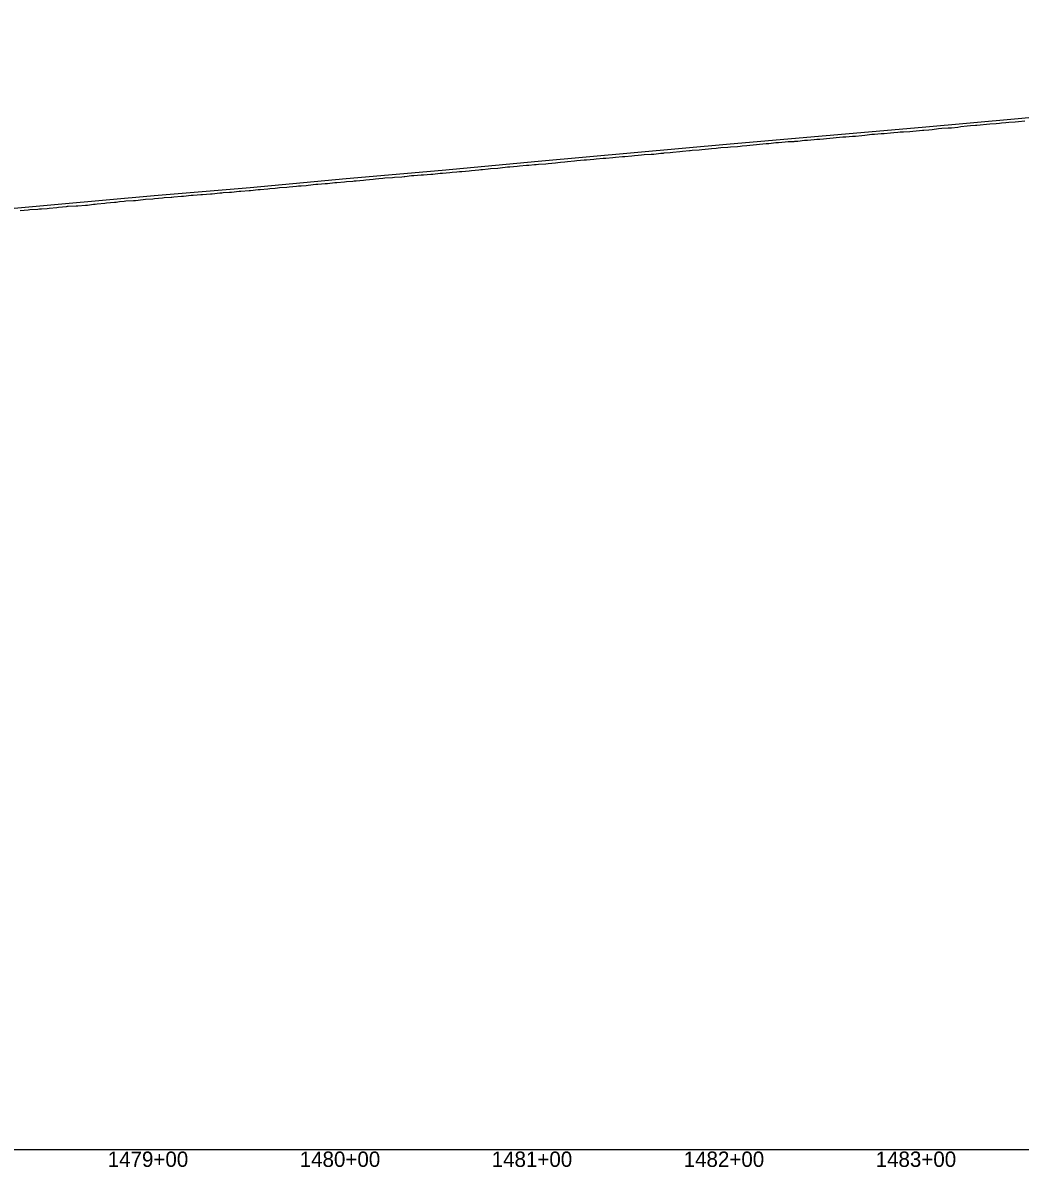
# Model space of a CAD drawing. Extents: x -3793 to 50787, y -1075 to 6138.
# Drawn here: x 35158 to 35677, y 2991 to 3587 of the extents above; entities that cross this region are included whole.
import ezdxf

# ---------------------------------------------------------------- set-up
doc = ezdxf.new("R2010")
doc.units = 0
for name, color, linetype in [('RD_DDB_Profile_EX', 7, 'Continuous'), ('RD_DDB_Profile_PR', 7, 'Continuous'), ('RD_DDB_StaTX', 7, 'Continuous'), ('RD_GPK_Profile_Cell', 7, 'Continuous')]:
    doc.layers.add(name, color=color, linetype=linetype)

msp = doc.modelspace()

# ---------------------------------------------------------------- linework, layer by layer
at = {"layer": 'RD_DDB_Profile_EX'}
for points in [[(35654.442955, 3533.8516), (35656.122863, 3534.02036), (35659.435395, 3534.352475), (35661.122604, 3534.47096), (35664.432271, 3534.73592), (35666.122365, 3534.88873), (35667.281431, 3534.99312), (35669.427147, 3535.18647), (35671.122255, 3535.339815), (35674.421361, 3535.604105), (35676.122204, 3535.74066), (35679.417078, 3536.07051)], [(35436.114327, 3514.36409), (35437.532631, 3514.506355), (35439.849509, 3514.73888), (35441.111273, 3514.878405), (35444.83487, 3515.252895), (35446.110788, 3515.3552), (35449.834512, 3515.690965), (35451.115232, 3515.819745), (35454.818988, 3516.15529), (35456.112334, 3516.259255), (35459.804357, 3516.519755), (35461.112043, 3516.624945), (35464.801593, 3516.921045), (35466.116606, 3517.04029), (35469.784618, 3517.409595), (35471.113852, 3517.48986), (35474.772148, 3517.78397), (35476.113813, 3517.91872), (35478.076537, 3518.135445), (35479.764547, 3518.321915), (35481.118484, 3518.43059), (35484.752141, 3518.65009), (35486.11593, 3518.759595), (35489.736495, 3519.160205), (35491.113338, 3519.28449), (35491.591172, 3519.322845), (35494.730462, 3519.57495), (35496.118163, 3519.700075), (35499.718198, 3520.097875), (35501.118539, 3520.252085), (35504.710676, 3520.612495), (35505.105807, 3520.64026), (35506.116202, 3520.711295), (35509.702573, 3520.89121), (35511.114022, 3521.047085), (35514.698144, 3521.513715), (35516.118965, 3521.656335), (35518.620443, 3521.8824), (35519.686463, 3521.978785), (35521.11682, 3522.093555), (35524.675165, 3522.415215), (35526.117622, 3522.50206), (35529.665416, 3522.75155), (35531.115555, 3522.91168), (35532.135078, 3522.9935), (35534.655445, 3523.195875), (35536.113648, 3523.342445), (35539.648611, 3523.76766), (35541.118812, 3523.88567), (35544.636196, 3524.1685), (35545.649713, 3524.280485), (35546.116889, 3524.332125), (35549.621545, 3524.68447), (35551.118103, 3524.84962), (35554.612729, 3525.1305), (35556.11638, 3525.236545), (35559.164349, 3525.359815), (35559.604552, 3525.37764), (35561.121684, 3525.51463), (35564.594362, 3525.89841), (35566.120152, 3526.02058), (35569.58556, 3526.368685), (35571.118601, 3526.49169), (35572.678984, 3526.570325), (35574.574973, 3526.665965), (35576.117176, 3526.78954), (35579.568158, 3527.17029), (35581.115824, 3527.29454), (35584.556892, 3527.640215), (35586.193619, 3527.80076), (35589.556027, 3528.003785), (35591.123223, 3528.129725), (35594.543668, 3528.473655), (35596.122005, 3528.631775), (35599.708255, 3529.026455), (35601.120813, 3529.16827), (35604.519339, 3529.408095), (35606.119755, 3529.504445), (35609.510353, 3529.81087), (35611.11872, 3530.00458), (35613.22289, 3530.174225), (35614.496664, 3530.27699), (35616.117756, 3530.37468), (35619.490168, 3530.545055), (35621.123576, 3530.709295), (35624.475673, 3531.080615), (35626.122634, 3531.21317), (35626.737525, 3531.244325), (35629.460588, 3531.382455), (35631.125189, 3531.532665), (35634.455632, 3532.033605), (35636.124518, 3532.15116), (35639.451834, 3532.417235), (35640.252161, 3532.417355), (35641.123978, 3532.41751), (35644.448558, 3532.75), (35646.123594, 3533.035035), (35649.44658, 3533.367375), (35651.12319, 3533.58595), (35653.766796, 3533.79747), (35654.442955, 3533.8516)], [(35216.122849, 3494.61629), (35220.179647, 3495.10328), (35221.298465, 3495.189405), (35225.179654, 3495.42267), (35226.122259, 3495.5174), (35230.173267, 3495.963375), (35231.118935, 3496.039285), (35234.813101, 3496.334485), (35235.176596, 3496.36355), (35236.121859, 3496.43962), (35240.16898, 3496.76385), (35241.118657, 3496.84964), (35245.171161, 3497.254665), (35246.121657, 3497.340675), (35248.327736, 3497.495325), (35250.163078, 3497.624085), (35251.118549, 3497.70054), (35255.158359, 3498.025345), (35256.121578, 3498.10275), (35260.14667, 3498.547085), (35261.116566, 3498.615115), (35261.842371, 3498.658905), (35265.139273, 3498.857945), (35266.121607, 3498.96625), (35270.128306, 3499.368725), (35271.116713, 3499.42821), (35275.357007, 3499.69133), (35276.121801, 3499.760245), (35280.105729, 3500.20122), (35281.116972, 3500.272395), (35285.099459, 3500.631735), (35286.122206, 3500.74431), (35288.871642, 3501.048485), (35290.084429, 3501.182715), (35291.117431, 3501.28651), (35295.076927, 3501.56492), (35296.122787, 3501.66967), (35300.061099, 3502.066375), (35301.11808, 3502.14084), (35302.386277, 3502.23001), (35305.052928, 3502.417635), (35306.123527, 3502.5035), (35310.039574, 3502.97563), (35311.118986, 3503.073275), (35315.034364, 3503.348005), (35316.124513, 3503.468135), (35320.027162, 3503.89846), (35321.120181, 3503.98647), (35325.013064, 3504.26037), (35326.11583, 3504.37093), (35329.415548, 3504.701115), (35330.011985, 3504.76083), (35331.121585, 3504.78303), (35335.001886, 3505.17233), (35336.117373, 3505.362165), (35339.993158, 3505.673305), (35341.11319, 3505.76322), (35342.930183, 3505.98172), (35344.986997, 3506.22915), (35346.11907, 3506.34232), (35349.975823, 3506.61401), (35351.114986, 3506.70531), (35354.973493, 3506.93753), (35356.118659, 3507.05226), (35356.444819, 3507.091595), (35359.959305, 3507.515625), (35361.116993, 3507.59672), (35364.950542, 3507.866345), (35366.113069, 3507.95976), (35369.959454, 3508.191105), (35371.116898, 3508.2956), (35374.940667, 3508.717335), (35376.115501, 3508.83492), (35379.934214, 3509.14141), (35381.111762, 3509.24772), (35383.474089, 3509.48373), (35384.936035, 3509.629865), (35386.115764, 3509.7248), (35389.925015, 3510.03068), (35391.114527, 3510.1617), (35394.9174, 3510.543325), (35396.110922, 3510.6631), (35396.988725, 3510.75102), (35399.914201, 3511.0442), (35401.115029, 3511.152735), (35404.906497, 3511.45677), (35406.114009, 3511.58988), (35409.897731, 3512.007775), (35410.50336, 3512.05634), (35411.110569, 3512.105065), (35414.894064, 3512.48437), (35416.114796, 3512.606985), (35419.881752, 3512.909965), (35421.113913, 3513.021215), (35424.017995, 3513.283905), (35424.871664, 3513.36117), (35426.110651, 3513.460655), (35429.862705, 3513.68684), (35431.107497, 3513.787075), (35434.856557, 3514.238165), (35436.114327, 3514.36409)], [(35156.13058, 3489.359445), (35160.23476, 3489.730185), (35161.124667, 3489.81965), (35165.229824, 3490.066765), (35166.128749, 3490.121185), (35167.239924, 3490.19933), (35170.217038, 3490.408835), (35171.122917, 3490.49092), (35175.21082, 3490.90071), (35176.127134, 3490.99239), (35180.200035, 3491.483015), (35180.754559, 3491.532945), (35181.123201, 3491.566155), (35185.196209, 3491.730275), (35186.125678, 3491.804895), (35190.186116, 3492.130895), (35191.121914, 3492.19653), (35194.269195, 3492.57508), (35195.181954, 3492.684915), (35196.124406, 3492.77947), (35200.177989, 3493.22536), (35201.120852, 3493.366925), (35205.183844, 3493.69111), (35206.12353, 3493.7572), (35207.78383, 3493.9398), (35210.179309, 3494.203385), (35211.120055, 3494.28808), (35215.18481, 3494.53147), (35216.122849, 3494.61629)]]:
    msp.add_lwpolyline(points, dxfattribs=at)
at = {"layer": 'RD_DDB_Profile_PR'}
msp.add_lwpolyline([(35125.9, 3488.114), (35175.9, 3492.569), (35225.9, 3497.0945), (35275.9, 3501.3395), (35325.9, 3505.9485), (35375.9, 3510.4125), (35425.9, 3515.043), (35475.9, 3519.4965), (35525.9, 3524.0885), (35575.9, 3528.3715), (35625.9, 3532.7945), (35675.9, 3537.322), (35725.9, 3541.913), (35775.9, 3546.5925), (35825.9, 3550.945), (35875.9, 3555.4815), (35925.9, 3559.818), (35975.9, 3564.4505), (36025.9, 3568.956), (36075.9, 3573.5635), (36125.9, 3577.9215), (36175.9, 3582.4645), (36225.9, 3587.095)], dxfattribs=at)
at = {"layer": 'RD_GPK_Profile_Cell'}
msp.add_line((1000, 3000), (46549.603806, 3000), dxfattribs=at)

# ---------------------------------------------------------------- texts
at = {"layer": 'RD_DDB_StaTX'}
for s, p in [('1479+00', (35201.687695, 2991)), ('1479+00', (35201.695471, 2991)), ('1480+00', (35301.687695, 2991)), ('1480+00', (35301.695471, 2991)), ('1481+00', (35401.687695, 2991)), ('1481+00', (35401.695471, 2991)), ('1482+00', (35501.687695, 2991)), ('1482+00', (35501.695471, 2991)), ('1483+00', (35601.687695, 2991)), ('1483+00', (35601.695471, 2991))]:
    msp.add_text(s, height=8, dxfattribs=at).set_placement(p)

doc.saveas('drawing.dxf')
